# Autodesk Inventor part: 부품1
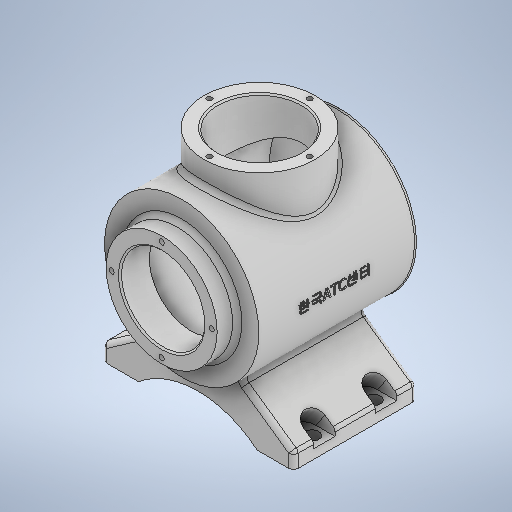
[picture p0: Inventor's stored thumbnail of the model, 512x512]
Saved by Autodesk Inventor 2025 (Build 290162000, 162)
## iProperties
Created: 2024-07
Part Number: 부품1
Material: 일반
Document SubType Name: Modeling
Designer: 학생
Density: 1 g/cm^3
Appearance: 기본값
Author: 학생
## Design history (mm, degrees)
sketch "스케치2"
  geometry: C1 r 50 at (0, 0); 1 further point
  constraints: 1 centre point, 1 coincident
  dimensions: "d10" = 100 diameter of C1
extrude "돌출1" new body sketch "스케치2" stored distance "d11" = 101; taper "d12" = 0 deg
sketch "스케치3"
  geometry: C1 r 36 at (0, 0); 1 further point
  constraints: 1 centre point, 1 coincident
  dimensions: "d13" = 72 diameter of C1
extrude "돌출2" join sketch "스케치3" distance "d14" = 13; taper "d15" = 0 deg
sketch "스케치4"
  geometry: L1 (-112.239, 0)-(112.239, 0); L2 (0, 77)-(0, -77); L3 (-38.5, -77)-(38.5, -77); L4 (38.5, -77)-(62, -77); L5 (62, -77)-(62, -67); L6 (62, -67)-(23.542, -40.072); L7 (-62, -67)-(-23.542, -40.072); L8 (-62, -77)-(-62, -67); L9 (-38.5, -77)-(-62, -77); L10 (-23.542, -40.072)-(23.542, -40.072); A1 r 59.937 centre (0, -122.937) between (38.5, -77) and (-38.5, -77); 3 further points
  constraints: 20 end point, 4 horizontal, 3 midpoint, 3 point on circle, 3 symmetric about line, 1 centre point, 1 coincident, 1 perpendicular, 1 vertical
  dimensions: "d16" = 77 distance of L2.end point (0, 0); "d17" = 77 distance of L3.start L3.end; "d18" = 23.5 distance of L3.end L4.end; "d19" = 10 distance of L4.end L5.end; "d20" = 55 deg angle of L5 L6; "d21" = 14 distance of L2.end point (0, -63)
extrude "돌출3" join sketch "스케치4" stored distance "d22" = 80; taper "d23" = 0 deg
node "작업 평면1"
sketch "스케치5"
  geometry: C1 r 36 at (0, 0); 1 further point
  constraints: 1 centre point, 1 coincident
  dimensions: "d25" = 72 diameter of C1
extrude "돌출4" join sketch "스케치5" distance "d26" = 15; taper "d27" = 0 deg
extrude "돌출5" join sketch "스케치5" stored distance "d28" = 15; taper "d29" = 0 deg
sketch "스케치6"
  geometry: L1 (0, 87.322)-(0, -87.322); L2 (-50, -50.5)-(50, -50.5) reference; A1 r 113 centre (9.729, 55.08) between (0, -57.5) and (50, -50.5); 2 further points
  constraints: 2 end point, 2 point on circle, 1 centre point, 1 coincident, 1 midpoint, 1 point on line, 1 vertical
  dimensions: "d30" = 7 distance from line of A1.start L2; "d34" = 113 radius of A1
feature "회전 곡면1" sketch "스케치6" dims angle "d31" = 90 deg
feature "두껍게 하기1" dims "d32" = 1, "d33" = 1
sketch "스케치7"
  geometry: C1 r 36 at (0, 0) reference; 2 further points
  constraints: 1 coincident
hole "구멍1" sketch "스케치7" at (0, 0) diameter "d35" = 54; stored, may be unused: countersink angle "d39" = 90 deg, drill point angle "d41" = 0 deg; dims "d36" = 6, "d37" = 4, "d38" = 2, "d40" = 19
sketch "스케치8"
  geometry: C1 r 27 at (0, 0) reference; 2 further points
  constraints: 1 coincident
hole "구멍2" sketch "스케치8" at (0, 0) diameter "d42" = 86; stored, may be unused: countersink angle "d46" = 90 deg, drill point angle "d48" = 0 deg; dims "d43" = 6, "d44" = 4, "d45" = 2, "d47" = 94
sketch "스케치9"
  geometry: C1 r 36 at (0, 0) reference; 2 further points
  constraints: 1 coincident
hole "구멍3" sketch "스케치9" at (0, 0) diameter "d49" = 54; stored, may be unused: countersink angle "d53" = 90 deg, drill point angle "d55" = 0 deg; dims "d50" = 6, "d51" = 4, "d52" = 2, "d54" = 40
sketch "스케치10"
  geometry: A1 r 32.5 centre (0, 0) between (0, 32.5) and (-32.5, 0); 3 further points
  constraints: 4 point on circle, 1 centre point, 1 coincident
  dimensions: "d56" = 65 diameter of A1
hole "구멍4" sketch "스케치10" at (0, 32.5), (-32.5, 0), (32.5, 0), (0, -32.5) diameter "d57" = 3.45873; stored, may be unused: countersink angle "d61" = 90 deg, drill point angle "d63" = 120 deg; dims "d58" = 8, "d59" = 4, "d60" = 2, "d62" = 10
sketch "스케치11"
  geometry: A1 r 32.5 centre (0, 0) between (-32.5, 0) and (0, -32.5); 3 further points
  constraints: 4 point on circle, 1 centre point, 1 coincident
  dimensions: "d64" = 65 diameter of A1
hole "구멍5" sketch "스케치11" at (-32.5, 0), (0, -32.5), (32.5, 0), (0, 32.5) diameter "d65" = 3.45873; stored, may be unused: countersink angle "d69" = 90 deg, drill point angle "d71" = 120 deg; dims "d66" = 8, "d67" = 4, "d68" = 2, "d70" = 10
fillet "모깎기1" dims "d72" = 3
chamfer "모따기1" distance "d73" = 1; stored, may be unused: second distance "d74" = 2, angle "d75" = 45 deg
fillet "모깎기2" dims "d76" = 3
chamfer "모따기2" distance "d77" = 1; stored, may be unused: second distance "d78" = 2, angle "d79" = 45 deg
sketch "스케치12"
  geometry: L1 (-38.793, 80)-(0, 80) reference; L2 (0, 80)-(0, 0) reference; L3 (-8, 53)-(8.451, 53); L4 (-8, 67)-(8.451, 67); L5 (8.451, 67)-(8.451, 53); A1 r 7 centre (-8, 60) between (-8, 53) and (-8, 67); 1 further point
  constraints: 6 end point, 2 horizontal, 2 point on circle, 1 centre point, 1 perpendicular
  dimensions: "d80" = 14 diameter of A1; "d81" = 20 distance from line of L1 A1.centre; "d82" = 8 distance from line of A1.centre L2
sketch "스케치13"
  geometry: L1 (23.5, -80)-(23.5, 0) reference; L2 (23.5, -80)-(0, -80) reference; C1 r 4.5 at (15.5, -60); 1 further point
  constraints: 1 centre point
  dimensions: "d83" = 9 diameter of C1; "d85" = 20 distance from line of C1.centre L2; "d86" = 8 distance from line of L1 C1.centre
extrude "돌출6" cut sketch "스케치13" distance "d87" = 6; taper "d88" = 0 deg
extrude "돌출7" cut sketch "스케치12" stored distance "d89" = 16; taper "d90" = 0 deg
fillet "모깎기3" dims "d91" = 3
node "작업 평면2"
sketch "스케치14"
  geometry: L1 (-77, -37)-(-77, 37) reference; L2 (36, 63.5)-(-36, 63.5) reference; 3 further points
  constraints: 1 midpoint, 1 other
  dimensions: "d93" = 77 horizontal distance of point (-77, 0) point (0, 1.5); "d94" = 62 distance from line of L2 point (0, 1.5)
feature "엠보싱1" sketch "스케치14" dims "d12" = 0, "d16" = 77, "d17" = 77, "d18" = 23.5, "d19" = 10, "d20" = 55 deg, "d21" = 14, "d95" = 0.5, "d96" = 0
node "솔리드1"
mirror "미러1"
mirror "미러2"
mirror "미러3"
mirror "미러4"
body "Srf1"
feature "A9D066F2-1C7D-4E18-AEED-F7BC21143FA4" dims "d35" = 54, "d36" = 6, "d37" = 4, "d38" = 2, "d39" = 90 deg, "d40" = 19, "d41" = 0
